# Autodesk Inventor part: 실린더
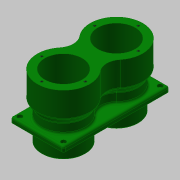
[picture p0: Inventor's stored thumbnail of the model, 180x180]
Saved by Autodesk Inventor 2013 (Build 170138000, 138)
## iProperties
Created: 2016-11
Part Number: 실린더
Material: 알루미늄 6061
Document SubType Name: Modeling
Designer: mduedu
Density: 2.71 g/cm^3
Mass: 592.083 g
Surface Area: 591.531 cm^2
Volume: 218.481 cm^3
Author: mduedu
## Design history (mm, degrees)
sketch "스케치1"
  geometry: L1 (0, 0)-(0, 101); L2 (30, 0)-(30, 101); L3 (30, 101)-(42, 101); L4 (42, 101)-(42, 61); L5 (42, 61)-(35, 51); L6 (35, 51)-(35, 0); L7 (35, 0)-(30, 0)
  constraints: 14 end point, 4 parallel, 2 horizontal alignment, 1 perpendicular, 1 vertical
  dimensions: "d0" = 101 distance of L1.start L1.end; "d1" = 60 diameter of L2.end L1; "d2" = 84 diameter of L3.end L1; "d3" = 70 diameter of L6.end L1; "d4" = 40 distance of L3.end L4.end; "d5" = 50 vertical distance of L5.end L3.end
revolve "회전1" stored, may be unused: angle "d6" = 90 deg
node "작업 평면1"
sketch "스케치2"
  geometry: L1 (-42.5, -42.5)-(42.5, -42.5); L2 (42.5, -42.5)-(42.5, 42.5); L3 (42.5, 42.5)-(-42.5, 42.5); L4 (-42.5, 42.5)-(-42.5, -42.5); L5 (-42.5, -42.5)-(42.5, 42.5); L6 (42.5, -42.5)-(-42.5, 42.5); C1 r 35 at (0, 0) reference; C2 r 35 at (0, 0); 1 further point
  constraints: 12 end point, 2 midpoint, 2 parallel, 2 perpendicular, 1 centre point, 1 coincident, 1 concentric, 1 horizontal
  dimensions: "d8" = 85 distance of L2.end L3.end
extrude "돌출1" join sketch "스케치2" distance "d10" = 8; taper "d11" = 0 deg
chamfer "모따기1" distance "d14" = 1; stored, may be unused: second distance "d15" = 2, angle "d16" = 45 deg
chamfer "모따기2" distance "d17" = 5; stored, may be unused: second distance "d18" = 2, angle "d19" = 15 deg
sketch "스케치3"
  geometry: L1 (-35, -35)-(35, -35); L2 (35, -35)-(35, 35); L3 (35, 35)-(-35, 35); L4 (-35, 35)-(-35, -35); L5 (-35, -35)-(35, 35); L6 (35, -35)-(-35, 35); 3 further points
  constraints: 12 end point, 2 coincident, 2 midpoint, 2 parallel, 1 horizontal, 1 perpendicular
  dimensions: "d20" = 70 distance of L3.end L2.end; "d21" = 70 distance of L2.end L1.end
sketch "스케치4"
  geometry: 2 further points
  constraints: 2 other
hole "구멍1" sketch "스케치4" at (-35, 35), (35, 35) diameter "d22" = 4.5; stored, may be unused: countersink angle "d26" = 90 deg, drill point angle "d28" = 0 deg; dims "d23" = 6, "d24" = 8, "d25" = 4.6, "d27" = 8
sketch "스케치5"
  geometry: 3 further points
  constraints: 3 other
hole "구멍2" sketch "스케치5" at (35, 0), (-35, 0), (0, 35) diameter "d29" = 4.134; stored, may be unused: countersink angle "d33" = 90 deg, drill point angle "d35" = 120 deg; dims "d30" = 7.5, "d31" = 4, "d32" = 2, "d34" = 10
fillet "모깎기3" dims "d36" = 3
fillet "모깎기4" dims "d37" = 3
sketch "스케치6"
  geometry: L1 (0, 0)-(0, -85); A1 r 42 centre (0, 0) between (32.469, -26.642) and (-32.469, -26.642) reference; A2 r 42 centre (0, -85) between (32.469, -58.358) and (-32.469, -58.358) reference; A3 r 25 centre (51.795, -42.5) between (32.469, -58.358) and (32.469, -26.642); A4 r 25 centre (-51.795, -42.5) between (-32.469, -26.642) and (-32.469, -58.358); A5 r 25 centre (51.795, -42.5) between (32.469, -26.642) and (32.469, -58.358); A6 r 25 centre (-51.795, -42.5) between (-32.469, -58.358) and (-32.469, -26.642); A7 r 42 centre (0, 0) between (-32.469, -26.642) and (32.469, -26.642); A8 r 42 centre (0, -85) between (32.469, -58.358) and (-32.469, -58.358); A9 r 42 centre (0, 0) between (32.469, -26.642) and (-32.469, -26.642); A10 r 42 centre (0, -85) between (-32.469, -58.358) and (32.469, -58.358); 1 further point
  constraints: 20 point on circle, 8 centre point, 2 coincident, 2 end point, 2 tangent, 1 symmetric about line, 1 vertical, 1 other
  dimensions: "d38" = 50 diameter of A3
node "작업 평면2"
sketch "스케치7"
  geometry: A1 r 25 centre (9.795, -42.5) between (-9.531, -26.642) and (-9.531, -58.358) reference; A2 r 42 centre (-42, 0) between (-74.469, -26.642) and (-9.531, -26.642) reference; A3 r 42 centre (-42, -85) between (-9.531, -58.358) and (-74.469, -58.358) reference; A4 r 25 centre (-93.795, -42.5) between (-74.469, -58.358) and (-74.469, -26.642) reference; 1 further point
node "작업 평면3"
sketch "스케치8"
  geometry: L1 (-35, 0)-(-35, -85); A1 r 35 centre (-35, 0) between (-10.294, -24.792) and (-59.706, -24.792) reference; A2 r 35 centre (-35, -85) between (-10.294, -60.208) and (-59.706, -60.208) reference; A3 r 25 centre (7.353, -42.5) between (-10.294, -60.208) and (-10.294, -24.792); A4 r 25 centre (-77.353, -42.5) between (-59.706, -24.792) and (-59.706, -60.208); A5 r 25 centre (7.353, -42.5) between (-10.294, -24.792) and (-10.294, -60.208); A6 r 25 centre (-77.353, -42.5) between (-59.706, -60.208) and (-59.706, -24.792); A7 r 35 centre (-35, 0) between (-59.706, -24.792) and (-10.294, -24.792); A8 r 35 centre (-35, -85) between (-10.294, -60.208) and (-59.706, -60.208); 1 further point
  constraints: 16 point on circle, 6 centre point, 2 coincident, 2 end point, 2 tangent, 1 symmetric about line, 1 vertical, 1 other
  dimensions: "d40" = 50 diameter of A3
sketch "스케치9"
  geometry: A1 r 25 centre (42.353, -42.5) between (24.706, -24.792) and (24.706, -60.208) reference; A2 r 35 centre (0, 0) between (-24.706, -24.792) and (24.706, -24.792) reference; A3 r 35 centre (0, -85) between (24.706, -60.208) and (-24.706, -60.208) reference; A4 r 25 centre (-42.353, -42.5) between (-24.706, -60.208) and (-24.706, -24.792) reference; 1 further point
feature "로프트1" sketch "스케치8", "스케치9" dims "d42" = 0, "d43" = 90 deg, "d44" = 0, "d45" = 90 deg
feature "로프트2" dims "d46" = 0, "d47" = 90 deg, "d48" = 0, "d49" = 90 deg
  node "모서리1"
feature "로프트3" dims "d50" = 0, "d51" = 90 deg, "d52" = 0, "d53" = 90 deg
  node "모서리2"
fillet "모깎기5" dims "d54" = 3
node "솔리드1"
mirror "대칭1"
other parameters: "d7" = -27
